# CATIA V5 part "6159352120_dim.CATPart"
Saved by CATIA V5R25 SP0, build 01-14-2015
Part number: 6159352120_dim
Source: made
Property "PROI_CREATED_ON": "12/17/2008 9:21:37 AM"
Property "BLANK_DRAWING": "--"
Property "DRAWN_BY": "FPA"
Property "FINISH": "--"
Property "HEAT_TREATMENT": "ASSIGN"
Property "MATERIAL": "ASSIGN"
Property "PROJECT": "--"
Property "PROTOTYPE_NO": "--"
Property "RELATED_DRAWING": "--"
Property "COMPLETE_MATERIAL": "ASSIGN-ASSIGN"
Property "DESCRIPTION": "Q-SHIELD 200-S"
Property "DRAWING_EXIST": "--"
Property "MANUFACTURER": "--"
Property "MANUFACTURER_2": "--"
Property "MANUFACTURER_REF": "--"
Property "TYPE_PART": "--"
Property "TODAY_DATE": "2021/06/10"
Property "PDMREV": "01.0"
Property "PDMRL": "Production"
Property "PROI_REVISION": "01"
Property "PROI_VERSION": "0"
Property "PROI_RELEASE": "Production"
Property "PTC_MODIFIED": false
Property "MFG_WP_MATERIAL": "ASSIGN"
Property "COMPANY_CODE": "---"
Property "DESCRIPTION_JP": "--"
Property "PQP_DOCUMENT": "--"
Property "GHOST": false
Property "NO_PART": false
Property "PTC_WM_ITERATION": "0"
Property "PTC_WM_VERSION": "01.0"
Property "PTC_WM_CREATED_ON": "10-Jun-21 10:43:32 AM"
Property "PTC_WM_MODIFIED_ON": "10-Jun-21 03:21:17 PM"
Property "PTC_WM_NAME": "6159352120_dim.prt"
Property "PTC_WM_NUMBER": "6159352120_DIM.PRT"
Property "PTC_WM_LIFECYCLE_STATE": "Production"
Property "PTC_WM_LIFECYCLE": "Design_Process"
Property "PTC_WM_REVISION": "01"
Property "PTC_WM_CREATED_BY": "Florian Pavageau (Grefpav) (Grefpav: CPD)"
Property "PTC_WM_MODIFIED_BY": "Florian Pavageau (Grefpav) (Grefpav: CPD)"
Property "PTC_ORGANIZATION_ID": "CPD"
Property "PTC_WM_LOCATION": "/Products/TORQUE MEASUREMENT SYSTEMS/A2010 - DELTAWRENCH GEN2/9-01-Dimensional D"
Property "PTC_WM_PART_NAME": "6159352120_dim.prt"
Property "PTC_WM_PART_NUMBER": "6159352120_DIM"
Property "PTC_WM_TEAM": "Default"
Property "EXPORT_CONTROL": "NULL"
Property "PTC_COMMON_NAME": "6159352120_dim.prt"
Property "PTC_MASTER_MATERIAL": "ASSIGN"
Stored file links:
  d:\ptc\Echange\temp\6159352120_dim.CATPart

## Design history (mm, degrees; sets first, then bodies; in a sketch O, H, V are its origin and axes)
AxisSystem1 "CS0": origin (0, 0, 0), X (1, 0, 0), Y (0, 1, 0), Z (0, 0, 1)
Set1
  DatumSurface1 "Sheet.1"
  DatumSurface2 "Sheet.2"
  DatumSurface3 "Sheet.3"
  DatumSurface4 "Sheet.4"
  DatumSurface5 "Sheet.5"
  DatumSurface6 "Sheet.6"
  DatumSurface7 "Sheet.7"
  DatumSurface8 "Sheet.8"
  Plane1 "RIGHT": stored without definition
  Plane2 "TOP": stored without definition
  Plane3 "FRONT": stored without definition
Body1 "PartBody" (main body)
